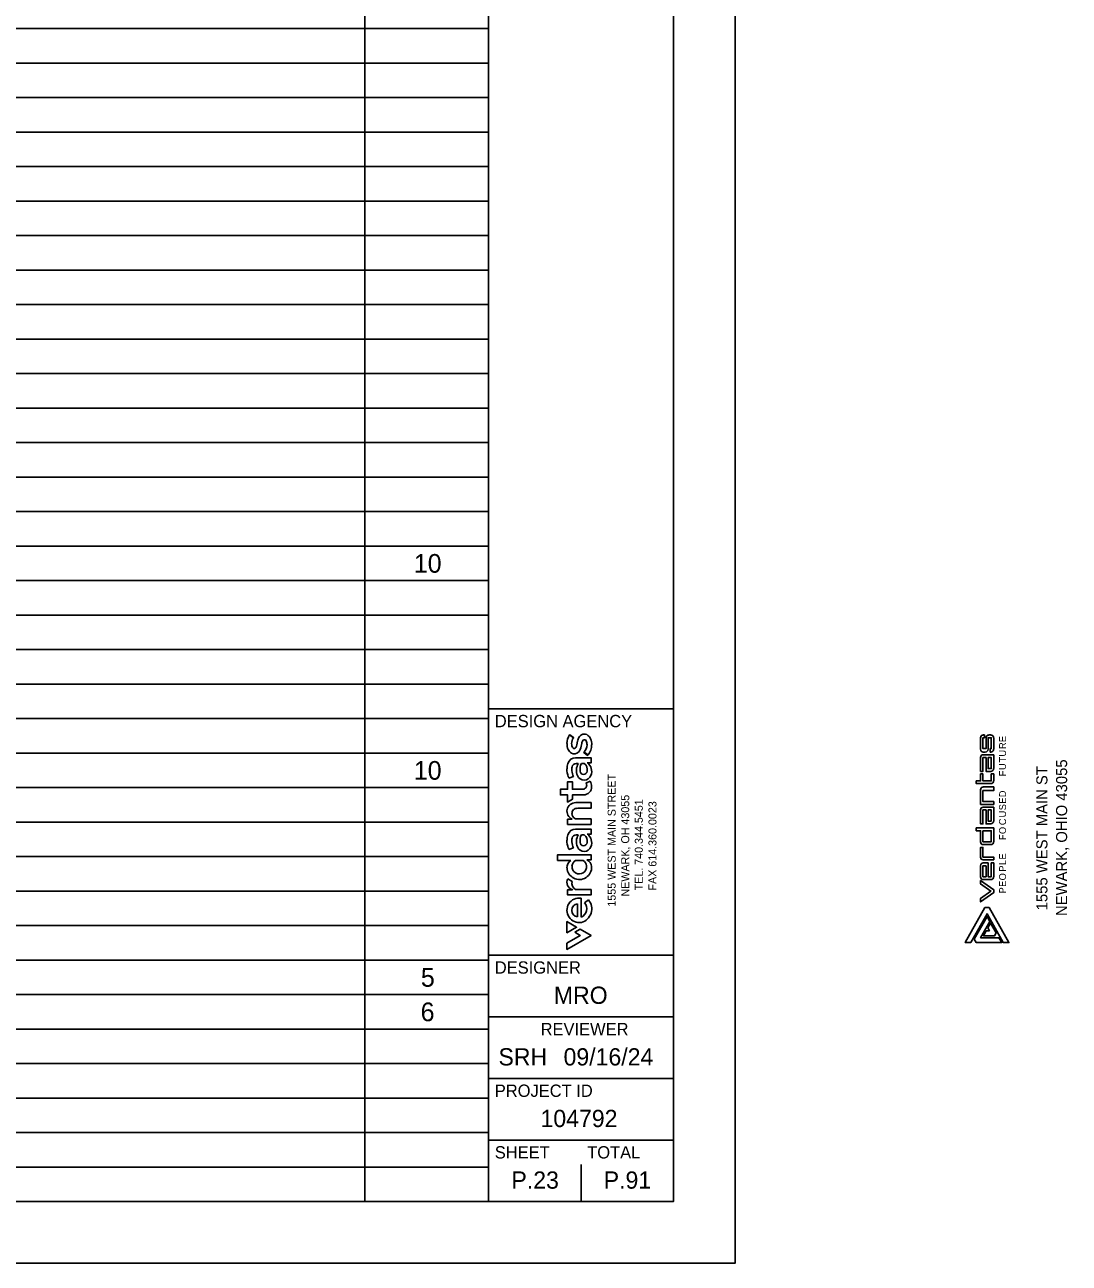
# Model space of a CAD drawing. Extents: x 0 to 36.7, y 0 to 22.
# Drawn here: x 28.24 to 36.71, y 0 to 10.05 of the extents above; entities that cross this region are included whole.
import ezdxf

# ---------------------------------------------------------------- set-up
doc = ezdxf.new("R2010")
doc.units = 0
for name, color, linetype in [('CS-ANNO-TTLB-LOGO', 7, 'Continuous'), ('Default', 7, 'Continuous'), ('SH_Border', 7, 'Continuous'), ('SH_Cut_Line', 7, 'Continuous'), ('SH_Data', 7, 'Continuous'), ('SH_Text', 7, 'Continuous')]:
    doc.layers.add(name, color=color, linetype=linetype)

msp = doc.modelspace()

# ---------------------------------------------------------------- linework, layer by layer
at = {"layer": 'CS-ANNO-TTLB-LOGO'}
for p, q in [((35.992, 4.264), (35.992, 4.171)), ((36.023, 4.287), (36.014, 4.287)), ((36.076, 4.287), (36.059, 4.287)), ((36.099, 4.171), (36.099, 4.264)), ((36.014, 4.149), (36.031, 4.149)), ((35.992, 3.991), (35.992, 4.104)), ((35.992, 3.566), (35.992, 3.679)), ((36.014, 3.398), (36.076, 3.398)), ((35.992, 3.226), (35.992, 3.136)), ((36.099, 3.136), (36.099, 3.249)), ((36.014, 3.114), (36.076, 3.114))]:
    msp.add_line(p, q, dxfattribs=at)
for points in [[(36.037, 4.264), (36.037, 4.177), (36.011, 4.177), (36.011, 4.264), (36.023, 4.264), (36.023, 4.287)], [(36.054, 4.171), (36.054, 4.264), (36.079, 4.264), (36.079, 4.177), (36.071, 4.177), (36.071, 4.149), (36.076, 4.149)], [(36.014, 4.126), (36.099, 4.126), (36.099, 4.014)], [(36.076, 3.991), (36.037, 3.991), (36.037, 4.104), (36.011, 4.104), (36.011, 3.991), (35.992, 3.991)], [(35.957, 3.915), (35.992, 3.915), (35.992, 3.971), (36.011, 3.971), (36.011, 3.915), (36.079, 3.915), (36.079, 3.971), (36.099, 3.971), (36.099, 3.915)], [(36.076, 3.893), (35.957, 3.893), (35.957, 3.915)], [(35.992, 3.842), (35.992, 3.724), (36.099, 3.724), (36.099, 3.746), (36.011, 3.746), (36.011, 3.836), (36.099, 3.836)], [(36.099, 3.836), (36.099, 3.865), (36.014, 3.865)], [(36.076, 3.566), (36.037, 3.566), (36.037, 3.679), (36.011, 3.679), (36.011, 3.566), (35.992, 3.566)], [(36.014, 3.701), (36.099, 3.701), (36.099, 3.589)], [(35.957, 3.533), (35.957, 3.51), (35.992, 3.51), (35.992, 3.42)], [(36.099, 3.42), (36.099, 3.533), (35.957, 3.533)], [(36.099, 3.296), (36.011, 3.296), (36.011, 3.375), (35.992, 3.375), (35.992, 3.296)], [(36.014, 3.274), (36.099, 3.274), (36.099, 3.296)], [(36.099, 3.249), (36.079, 3.249), (36.079, 3.136), (36.054, 3.136), (36.054, 3.249), (36.014, 3.249)]]:
    msp.add_lwpolyline(points, dxfattribs=at)
for points in [[(36.054, 4.104), (36.079, 4.104), (36.079, 4.014), (36.054, 4.014)], [(36.054, 3.679), (36.079, 3.679), (36.079, 3.589), (36.054, 3.589)], [(36.011, 3.51), (36.011, 3.42), (36.079, 3.42), (36.079, 3.51)], [(36.037, 3.226), (36.011, 3.226), (36.011, 3.136), (36.037, 3.136)], [(36.076, 3.02), (35.992, 2.961), (35.992, 2.933), (36.099, 3.008), (36.099, 3.031), (35.992, 3.106), (35.992, 3.079)]]:
    msp.add_lwpolyline(points, close=True, dxfattribs=at)
for centre, start, end in [((36.014, 4.264), 90, 180), ((36.059, 4.264), 90, 180), ((36.076, 4.264), 360, 90), ((36.014, 4.171), 180, 270), ((36.014, 4.104), 90, 180), ((36.031, 4.171), 270, 0), ((36.076, 4.171), 270, 0), ((36.076, 4.014), 270, 360), ((36.014, 3.842), 90, 180), ((36.076, 3.915), 270, 360), ((36.014, 3.679), 90, 180), ((36.076, 3.589), 270, 360), ((36.014, 3.42), 180, 270), ((36.076, 3.42), 270, 0), ((36.014, 3.296), 180, 270), ((36.014, 3.226), 90, 180), ((36.014, 3.136), 180, 270), ((36.076, 3.136), 270, 0)]:
    msp.add_arc(centre, 0.0225, start, end, dxfattribs=at)
at = {"layer": 'Default'}
for p, q in [((35.992, 4.264), (35.992, 4.171)), ((36.076, 4.287), (36.059, 4.287)), ((36.099, 4.171), (36.099, 4.264)), ((36.014, 4.149), (36.031, 4.149)), ((36.014, 3.398), (36.076, 3.398)), ((35.992, 3.226), (35.992, 3.136)), ((36.014, 3.114), (36.076, 3.114)), ((35.941, 2.63), (36.045, 2.813)), ((36.067, 2.773), (35.993, 2.641)), ((36.045, 2.813), (36.067, 2.773)), ((35.957, 2.602), (35.941, 2.63)), ((35.993, 2.641), (36.141, 2.641)), ((36.141, 2.641), (36.164, 2.602)), ((36.164, 2.602), (35.957, 2.602))]:
    msp.add_line(p, q, dxfattribs=at)
for points in [[(36.037, 4.264), (36.037, 4.177), (36.011, 4.177), (36.011, 4.264), (36.023, 4.264), (36.023, 4.287), (36.014, 4.287)], [(36.054, 4.171), (36.054, 4.264), (36.079, 4.264), (36.079, 4.177), (36.071, 4.177), (36.071, 4.149), (36.076, 4.149)], [(36.099, 4.014), (36.099, 4.126), (36.014, 4.126)], [(35.992, 4.104), (35.992, 3.991), (36.011, 3.991), (36.011, 4.104), (36.037, 4.104), (36.037, 3.991), (36.076, 3.991)], [(36.099, 3.915), (36.099, 3.971), (36.079, 3.971), (36.079, 3.915), (36.011, 3.915), (36.011, 3.971), (35.992, 3.971), (35.992, 3.915), (35.957, 3.915), (35.957, 3.893), (36.076, 3.893)], [(35.992, 3.842), (35.992, 3.724), (36.099, 3.724), (36.099, 3.746), (36.011, 3.746), (36.011, 3.836), (36.099, 3.836), (36.099, 3.865), (36.014, 3.865)], [(35.992, 3.679), (35.992, 3.566), (36.011, 3.566), (36.011, 3.679), (36.037, 3.679), (36.037, 3.566), (36.076, 3.566)], [(36.099, 3.589), (36.099, 3.701), (36.014, 3.701)], [(36.099, 3.42), (36.099, 3.533), (35.957, 3.533), (35.957, 3.51), (35.992, 3.51), (35.992, 3.42)], [(36.014, 3.274), (36.099, 3.274), (36.099, 3.296), (36.011, 3.296), (36.011, 3.375), (35.992, 3.375), (35.992, 3.296)], [(36.099, 3.136), (36.099, 3.249), (36.079, 3.249), (36.079, 3.136), (36.054, 3.136), (36.054, 3.249), (36.014, 3.249)]]:
    msp.add_lwpolyline(points, dxfattribs=at)
for points in [[(36.079, 4.104), (36.079, 4.014), (36.054, 4.014), (36.054, 4.104)], [(36.079, 3.679), (36.079, 3.589), (36.054, 3.589), (36.054, 3.679)], [(36.011, 3.51), (36.079, 3.51), (36.079, 3.42), (36.011, 3.42)], [(36.037, 3.226), (36.037, 3.136), (36.011, 3.136), (36.011, 3.226)], [(35.992, 2.961), (35.992, 2.933), (36.099, 3.008), (36.099, 3.031), (35.992, 3.106), (35.992, 3.079), (36.076, 3.02)], [(36.045, 2.836), (36.176, 2.602), (36.222, 2.602), (36.061, 2.887), (36.028, 2.887), (35.868, 2.602), (35.913, 2.602)], [(35.913, 2.602), (36.045, 2.836), (36.176, 2.602), (36.222, 2.602), (36.061, 2.887), (36.028, 2.887), (35.868, 2.602)], [(35.941, 2.63), (35.957, 2.602), (36.164, 2.602), (36.141, 2.641), (35.993, 2.641), (36.067, 2.773), (36.045, 2.813)], [(36.038, 2.698), (36.016, 2.658), (36.106, 2.658), (36.119, 2.681), (36.074, 2.761), (36.051, 2.721), (36.064, 2.698)], [(36.038, 2.698), (36.064, 2.698), (36.051, 2.721), (36.074, 2.761), (36.119, 2.681), (36.106, 2.658), (36.016, 2.658)]]:
    msp.add_lwpolyline(points, close=True, dxfattribs=at)
for centre, start, end in [((36.014, 4.264), 90, 180), ((36.059, 4.264), 90, 180), ((36.076, 4.264), 360, 90), ((36.014, 4.171), 180, 270), ((36.014, 4.104), 90, 180), ((36.031, 4.171), 270, 0), ((36.076, 4.171), 270, 0), ((36.076, 4.014), 270, 0), ((36.014, 3.842), 90, 180), ((36.076, 3.915), 270, 0), ((36.014, 3.679), 90, 180), ((36.076, 3.589), 270, 0), ((36.014, 3.42), 180, 270), ((36.076, 3.42), 270, 0), ((36.014, 3.296), 180, 270), ((36.014, 3.226), 90, 180), ((36.014, 3.136), 180, 270), ((36.076, 3.136), 270, 0)]:
    msp.add_arc(centre, 0.0225, start, end, dxfattribs=at)
at = {"layer": 'SH_Border'}
for p, q in [((32, 0.5), (32, 21.5)), ((32, 4.5), (33.5, 4.5)), ((32, 2.5), (33.5, 2.5)), ((32, 2), (33.5, 2)), ((32, 1.5), (33.5, 1.5)), ((32, 1), (33.5, 1))]:
    msp.add_line(p, q, dxfattribs=at)
msp.add_lwpolyline([(1.5, 21.5), (33.5, 21.5), (33.5, 0.5), (1.5, 0.5)], close=True, dxfattribs=at)
at = {"layer": 'SH_Cut_Line'}
msp.add_lwpolyline([(0, 0), (34, 0), (34, 22), (0, 22)], close=True, dxfattribs=at)
at = {"layer": 'SH_Data'}
for p, q in [((32.75, 3.5), (32.75, 3.5)), ((32.75, 0.5), (32.75, 0.8)), ((32.375, 0.675), (32.375, 0.675))]:
    msp.add_line(p, q, dxfattribs=at)
at = {"layer": 'SH_Text'}
for p, q in [((30.995, 21.5), (30.995, 0.5)), ((32, 21.5), (32, 0.5)), ((1.5, 10.02), (32, 10.02)), ((1.5, 9.74), (32, 9.74)), ((1.5, 9.46), (32, 9.46)), ((1.5, 9.18), (32, 9.18)), ((1.5, 8.9), (32, 8.9)), ((1.5, 8.62), (32, 8.62)), ((1.5, 8.34), (32, 8.34)), ((1.5, 8.06), (32, 8.06)), ((1.5, 7.78), (32, 7.78)), ((1.5, 7.5), (32, 7.5)), ((1.5, 7.22), (32, 7.22)), ((1.5, 6.94), (32, 6.94)), ((1.5, 6.66), (32, 6.66)), ((1.5, 6.38), (32, 6.38)), ((1.5, 6.1), (32, 6.1)), ((1.5, 5.82), (32, 5.82)), ((1.5, 5.54), (32, 5.54)), ((1.5, 5.26), (32, 5.26)), ((1.5, 4.98), (32, 4.98)), ((1.5, 4.7), (32, 4.7)), ((1.5, 4.42), (32, 4.42)), ((32.688, 4.264), (32.657, 4.288)), ((32.722, 4.238), (32.715, 4.207)), ((1.5, 4.14), (32, 4.14)), ((32.751, 4.197), (32.756, 4.217)), ((32.774, 4.149), (32.807, 4.125)), ((32.711, 4.056), (32.727, 4.056)), ((32.753, 4.056), (32.776, 4.056)), ((32.648, 3.948), (32.652, 3.936)), ((1.5, 3.86), (32, 3.86)), ((32.825, 3.913), (32.79, 3.896)), ((1.5, 3.58), (32, 3.58)), ((32.711, 3.478), (32.727, 3.478)), ((32.753, 3.478), (32.776, 3.478)), ((32.648, 3.37), (32.652, 3.358)), ((1.5, 3.3), (32, 3.3)), ((32.706, 3.269), (32.766, 3.269)), ((32.679, 3.098), (32.642, 3.12)), ((1.5, 3.02), (32, 3.02)), ((32.721, 2.918), (32.721, 2.81)), ((32.751, 2.809), (32.751, 2.962)), ((32.81, 2.948), (32.778, 2.926)), ((1.5, 2.74), (32, 2.74)), ((1.5, 2.46), (32, 2.46)), ((1.5, 2.18), (32, 2.18)), ((1.5, 1.9), (32, 1.9)), ((1.5, 1.62), (32, 1.62)), ((1.5, 1.34), (32, 1.34)), ((1.5, 1.06), (32, 1.06)), ((1.5, 0.78), (32, 0.78)), ((1.5, 0.5), (32, 0.5))]:
    msp.add_line(p, q, dxfattribs=at)
for points in [[(32.69, 4.267), (32.658, 4.289), (32.657, 4.288)], [(32.688, 4.264), (32.69, 4.267)], [(32.722, 4.238), (32.715, 4.207)], [(32.751, 4.197), (32.756, 4.217)], [(32.774, 4.149), (32.772, 4.146), (32.803, 4.121), (32.807, 4.125)], [(32.801, 4.06), (32.831, 4.06), (32.831, 4.102), (32.706, 4.102)], [(32.801, 4.06), (32.831, 4.06), (32.831, 4.102), (32.706, 4.102)], [(32.711, 4.056), (32.727, 4.056)], [(32.776, 4.056), (32.753, 4.056)], [(32.648, 3.948), (32.652, 3.936)], [(32.652, 3.936), (32.688, 3.951), (32.684, 3.96)], [(32.652, 3.936), (32.688, 3.951), (32.684, 3.96)], [(32.762, 3.847), (32.68, 3.847), (32.68, 3.908), (32.641, 3.908), (32.641, 3.847), (32.582, 3.847), (32.582, 3.801), (32.641, 3.801), (32.641, 3.742), (32.68, 3.765), (32.68, 3.801), (32.77, 3.801)], [(32.762, 3.847), (32.68, 3.847), (32.68, 3.908), (32.641, 3.908), (32.641, 3.847), (32.582, 3.847), (32.582, 3.801), (32.641, 3.801), (32.641, 3.742), (32.68, 3.765), (32.68, 3.801), (32.77, 3.801)], [(32.825, 3.913), (32.79, 3.896)], [(32.72, 3.692), (32.831, 3.692), (32.831, 3.738), (32.707, 3.738)], [(32.72, 3.692), (32.831, 3.692), (32.831, 3.738), (32.707, 3.738)], [(32.678, 3.603), (32.641, 3.603), (32.641, 3.561), (32.831, 3.561), (32.831, 3.606), (32.704, 3.606)], [(32.678, 3.603), (32.641, 3.603), (32.641, 3.561), (32.831, 3.561), (32.831, 3.606), (32.704, 3.606)], [(32.801, 3.481), (32.831, 3.481), (32.831, 3.523), (32.706, 3.523)], [(32.801, 3.481), (32.831, 3.481), (32.831, 3.523), (32.706, 3.523)], [(32.711, 3.478), (32.727, 3.478)], [(32.776, 3.478), (32.753, 3.478)], [(32.648, 3.37), (32.652, 3.358)], [(32.652, 3.358), (32.688, 3.372), (32.684, 3.382)], [(32.652, 3.358), (32.688, 3.372), (32.684, 3.382)], [(32.667, 3.269), (32.56, 3.269), (32.56, 3.315), (32.831, 3.315), (32.831, 3.273), (32.798, 3.273)], [(32.798, 3.273), (32.831, 3.273), (32.831, 3.315), (32.56, 3.315), (32.56, 3.269), (32.667, 3.269)], [(32.706, 3.269), (32.766, 3.269)], [(32.679, 3.098), (32.642, 3.12)], [(32.682, 3.031), (32.641, 3.031), (32.641, 2.989), (32.831, 2.989), (32.831, 3.033), (32.705, 3.033)], [(32.682, 3.031), (32.641, 3.031), (32.641, 2.989), (32.831, 2.989), (32.831, 3.033), (32.705, 3.033)], [(32.721, 2.81), (32.721, 2.918)], [(32.751, 2.809), (32.751, 2.962)], [(32.81, 2.948), (32.778, 2.926)], [(32.636, 2.773), (32.636, 2.682), (32.714, 2.727), (32.636, 2.773)], [(32.7, 2.686), (32.744, 2.66), (32.636, 2.597), (32.636, 2.547), (32.831, 2.66), (32.743, 2.711), (32.7, 2.686)]]:
    msp.add_lwpolyline(points, dxfattribs=at)
for points in [[(32.714, 2.727), (32.636, 2.682), (32.636, 2.773)], [(32.7, 2.686), (32.744, 2.66), (32.636, 2.597), (32.636, 2.547), (32.831, 2.66), (32.743, 2.711)]]:
    msp.add_lwpolyline(points, close=True, dxfattribs=at)
for centre, radius, start, end in [((32.767, 4.217), 0.131, 147.2233, 179.842), ((32.767, 4.217), 0.131, 147.2233, 179.842), ((32.768, 4.214), 0.0948, 148.1233, 178.1135), ((32.768, 4.214), 0.0948, 148.1233, 178.1135), ((32.849, 4.21), 0.13, 154.0447, 167.2149), ((32.849, 4.21), 0.13, 154.0447, 167.2149), ((32.776, 4.245), 0.0493, 52.7092, 154.2166), ((32.776, 4.245), 0.0493, 52.7092, 154.2166), ((32.849, 4.201), 0.0949, 158.1863, 170.6328), ((32.849, 4.201), 0.0949, 158.1863, 170.6328), ((32.777, 4.232), 0.0165, 26.9165, 163.602), ((32.777, 4.232), 0.0165, 26.9165, 163.602), ((32.733, 4.21), 0.0655, 357.0077, 26.3112), ((32.733, 4.21), 0.0655, 357.0077, 26.3112), ((32.761, 4.229), 0.0711, 22.8278, 50.7157), ((32.761, 4.229), 0.0711, 22.8278, 50.7157), ((32.717, 4.21), 0.12, 359.0192, 22.9257), ((32.717, 4.21), 0.12, 359.0192, 22.9257), ((32.75, 4.215), 0.114, 179.0109, 203.56), ((32.75, 4.215), 0.114, 179.0109, 203.56), ((32.707, 4.196), 0.067, 203.3692, 237.807), ((32.707, 4.196), 0.067, 203.3692, 237.807), ((32.695, 4.179), 0.0458, 238.9453, 317.6829), ((32.695, 4.179), 0.0458, 238.9453, 317.6829), ((32.744, 4.216), 0.0702, 179.0539, 195.6921), ((32.744, 4.216), 0.0702, 179.0539, 195.6921), ((32.709, 4.205), 0.0335, 193.8561, 223.7191), ((32.709, 4.205), 0.0335, 193.8561, 223.7191), ((32.695, 4.192), 0.0148, 224.7822, 330.4366), ((32.695, 4.192), 0.0148, 224.7822, 330.4366), ((32.635, 4.222), 0.0819, 332.9002, 349.3831), ((32.635, 4.222), 0.0819, 332.9002, 349.3831), ((32.648, 4.215), 0.105, 320.1259, 349.7023), ((32.648, 4.215), 0.105, 320.1259, 349.7023), ((32.706, 4.212), 0.0932, 317.363, 356.9244), ((32.706, 4.212), 0.0932, 317.363, 356.9244), ((32.707, 4.207), 0.129, 320.5166, 0.4341), ((32.707, 4.207), 0.129, 320.5166, 0.4341), ((32.764, 4.014), 0.128, 160.8128, 180.9317), ((32.764, 4.014), 0.128, 160.8128, 180.9317), ((32.704, 4.038), 0.0639, 88.076, 162.8642), ((32.704, 4.038), 0.0639, 88.076, 162.8642), ((32.739, 4.01), 0.0647, 163.2522, 179.9971), ((32.739, 4.01), 0.0647, 163.2522, 179.9971), ((32.713, 4.019), 0.0374, 92.9671, 165.223), ((32.713, 4.019), 0.0374, 92.9671, 165.223), ((32.82, 3.999), 0.108, 148.3497, 202.4708), ((32.82, 3.999), 0.108, 148.3497, 202.4708), ((32.847, 4.01), 0.105, 153.8372, 188.8746), ((32.847, 4.01), 0.105, 153.8372, 188.8746), ((32.737, 4.006), 0.0637, 348.1247, 52.3678), ((32.737, 4.006), 0.0637, 348.1247, 52.3678), ((32.751, 3.991), 0.0857, 338.2774, 53.7949), ((32.751, 3.991), 0.0857, 338.2774, 53.7949), ((32.834, 4.016), 0.199, 180.9467, 199.8354), ((32.834, 4.016), 0.199, 180.9467, 199.8354), ((32.826, 4.014), 0.152, 181.6616, 200.8714), ((32.826, 4.014), 0.152, 181.6616, 200.8714), ((32.775, 3.98), 0.0592, 201.6764, 339.7268), ((32.775, 3.98), 0.0592, 201.6764, 339.7268), ((32.771, 3.995), 0.0281, 182.327, 355.3778), ((32.771, 3.995), 0.0281, 182.327, 355.3778), ((32.764, 3.878), 0.0314, 265.0692, 356.3548), ((32.764, 3.878), 0.0314, 265.0692, 356.3548), ((32.772, 3.866), 0.0642, 267.8641, 1.6213), ((32.772, 3.866), 0.0642, 267.8641, 1.6213), ((32.753, 3.875), 0.0432, 1.8638, 29.9651), ((32.753, 3.875), 0.0432, 1.8638, 29.9651), ((32.742, 3.868), 0.0939, 359.5424, 28.2495), ((32.742, 3.868), 0.0939, 359.5424, 28.2495), ((32.706, 3.668), 0.0703, 88.9896, 246.9111), ((32.706, 3.668), 0.0703, 88.9896, 246.9111), ((32.72, 3.652), 0.0434, 137.3049, 182.9688), ((32.72, 3.652), 0.0434, 137.3049, 182.9688), ((32.724, 3.65), 0.0477, 180.3466, 244.9113), ((32.724, 3.65), 0.0477, 180.3466, 244.9113), ((32.717, 3.649), 0.0433, 86.9739, 132.7421), ((32.717, 3.649), 0.0433, 86.9739, 132.7421), ((32.704, 3.459), 0.0639, 88.076, 162.8642), ((32.704, 3.459), 0.0639, 88.076, 162.8642), ((32.764, 3.436), 0.128, 160.8128, 180.9317), ((32.764, 3.436), 0.128, 160.8128, 180.9317), ((32.834, 3.437), 0.199, 180.9467, 199.8354), ((32.834, 3.437), 0.199, 180.9467, 199.8354), ((32.739, 3.431), 0.0647, 163.2522, 179.9971), ((32.739, 3.431), 0.0647, 163.2522, 179.9971), ((32.826, 3.436), 0.152, 181.6616, 200.8714), ((32.826, 3.436), 0.152, 181.6616, 200.8714), ((32.713, 3.44), 0.0374, 92.9671, 165.223), ((32.713, 3.44), 0.0374, 92.9671, 165.223), ((32.82, 3.421), 0.108, 148.3497, 202.4708), ((32.82, 3.421), 0.108, 148.3497, 202.4708), ((32.847, 3.431), 0.105, 153.8372, 188.8746), ((32.847, 3.431), 0.105, 153.8372, 188.8746), ((32.737, 3.427), 0.0637, 348.1247, 52.3678), ((32.737, 3.427), 0.0637, 348.1247, 52.3678), ((32.751, 3.412), 0.0857, 338.2774, 53.7949), ((32.751, 3.412), 0.0857, 338.2774, 53.7949), ((32.775, 3.401), 0.0592, 201.6764, 339.7268), ((32.775, 3.401), 0.0592, 201.6764, 339.7268), ((32.771, 3.416), 0.0281, 182.327, 355.3778), ((32.771, 3.416), 0.0281, 182.327, 355.3778), ((32.707, 3.21), 0.0714, 124.2843, 181.2723), ((32.707, 3.21), 0.0714, 124.2843, 181.2723), ((32.736, 3.214), 0.1, 182.7719, 2.9779), ((32.736, 3.214), 0.1, 182.7719, 2.9779), ((32.735, 3.219), 0.0586, 119.9007, 175.5797), ((32.735, 3.219), 0.0586, 119.9007, 175.5797), ((32.736, 3.219), 0.0595, 176.4529, 5.055), ((32.736, 3.219), 0.0595, 176.4529, 5.055), ((32.737, 3.218), 0.0588, 6.0666, 60.041), ((32.737, 3.218), 0.0588, 6.0666, 60.041), ((32.769, 3.213), 0.0671, 5.3084, 64.5252), ((32.769, 3.213), 0.0671, 5.3084, 64.5252), ((32.698, 3.092), 0.0628, 152.6524, 255.2929), ((32.698, 3.092), 0.0628, 152.6524, 255.2929), ((32.731, 3.081), 0.0545, 162.1384, 242.0408), ((32.731, 3.081), 0.0545, 162.1384, 242.0408), ((32.735, 2.864), 0.0996, 81.0446, 280.2577), ((32.735, 2.864), 0.0996, 81.0446, 280.2577), ((32.729, 2.864), 0.0543, 98.8378, 261.1622), ((32.729, 2.864), 0.0543, 98.8378, 261.1622), ((32.725, 2.877), 0.072, 290.9232, 42.7391), ((32.725, 2.877), 0.072, 290.9232, 42.7391), ((32.723, 2.876), 0.114, 285.6668, 39.3699), ((32.723, 2.876), 0.114, 285.6668, 39.3699)]:
    msp.add_arc(centre, radius, start, end, dxfattribs=at)

# ---------------------------------------------------------------- texts
at = {"layer": 'Default'}
for s, p in [('E', (36.199, 4.229)), ('R', (36.199, 4.173)), ('U', (36.199, 4.112)), ('T', (36.199, 4.064)), ('U', (36.199, 4.003)), ('F', (36.199, 3.952)), ('D', (36.199, 3.782)), ('S', (36.199, 3.676)), ('E', (36.199, 3.729)), ('U', (36.199, 3.618)), ('C', (36.199, 3.555)), ('O', (36.199, 3.483)), ('F', (36.199, 3.434)), ('E', (36.199, 3.276)), ('L', (36.199, 3.231)), ('P', (36.199, 3.178)), ('O', (36.199, 3.107)), ('E', (36.199, 3.054)), ('P', (36.199, 3.001))]:
    msp.add_text(s, height=0.0563, rotation=90, dxfattribs=at).set_placement(p)
at = {"layer": 'SH_Data'}
for s, height, p in [('DESIGN AGENCY', 0.1, (32.05, 4.35)), ('DESIGNER', 0.1, (32.05, 2.35)), ('MRO', 0.14, (32.529, 2.105)), ('REVIEWER', 0.1, (32.422, 1.85)), ('SRH', 0.14, (32.08, 1.605)), ('09/16/24', 0.14, (32.608, 1.605)), ('PROJECT ID', 0.1, (32.05, 1.35)), ('104792', 0.14, (32.421, 1.105)), ('SHEET', 0.1, (32.05, 0.85)), ('TOTAL', 0.1, (32.8, 0.85)), ('P.23', 0.14, (32.185, 0.605)), ('P.91', 0.14, (32.934, 0.605))]:
    msp.add_text(s, height=height, dxfattribs=at).set_placement(p)
at = {"layer": 'SH_Text'}
for s, height, p in [('10', 0.1515, (31.393, 5.604)), ('10', 0.1515, (31.393, 3.924)), ('5', 0.152, (31.45, 2.244)), ('6', 0.152, (31.448, 1.964))]:
    msp.add_text(s, height=height, dxfattribs=at).set_placement(p)
for s, height, p in [('1555 WEST MAIN ST', 0.09, (36.535, 2.864)), ('NEWARK, OHIO 43055', 0.09, (36.695, 2.818)), ('1555 WEST MAIN STREET', 0.06497, (33.031, 2.894)), ('NEWARK, OH 43055', 0.06497, (33.141, 2.976)), ('TEL. 740.344.5451', 0.06497, (33.251, 3.026)), ('FAX 614.360.0023', 0.06497, (33.362, 3.025))]:
    msp.add_text(s, height=height, rotation=90, dxfattribs=at).set_placement(p)

doc.saveas('drawing.dxf')
